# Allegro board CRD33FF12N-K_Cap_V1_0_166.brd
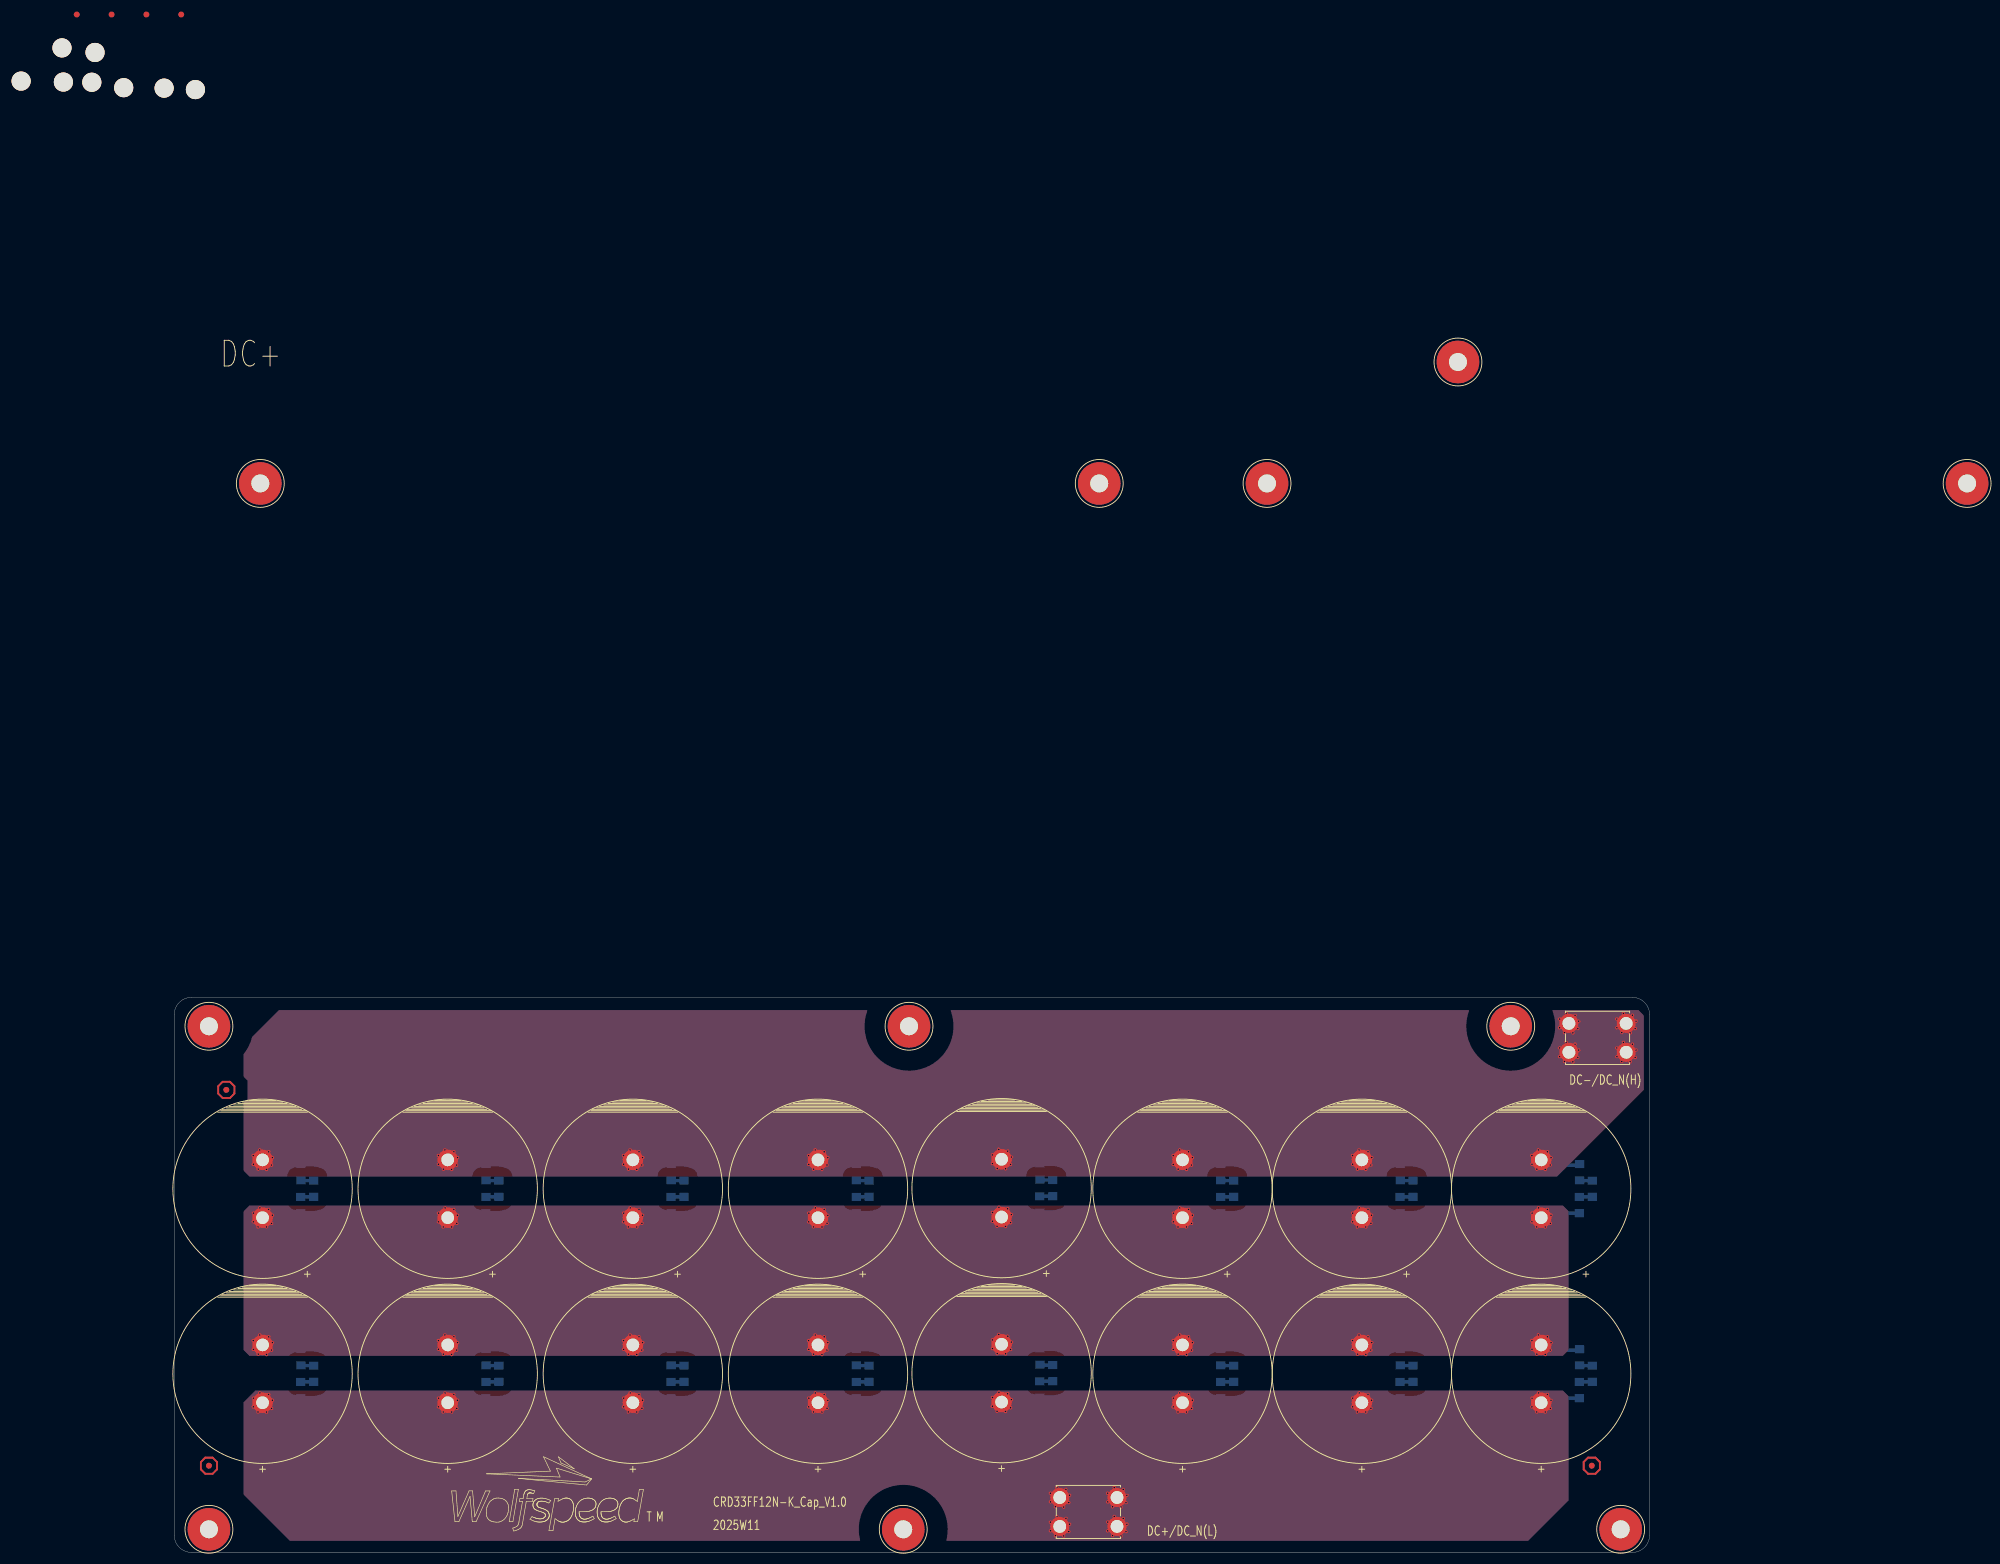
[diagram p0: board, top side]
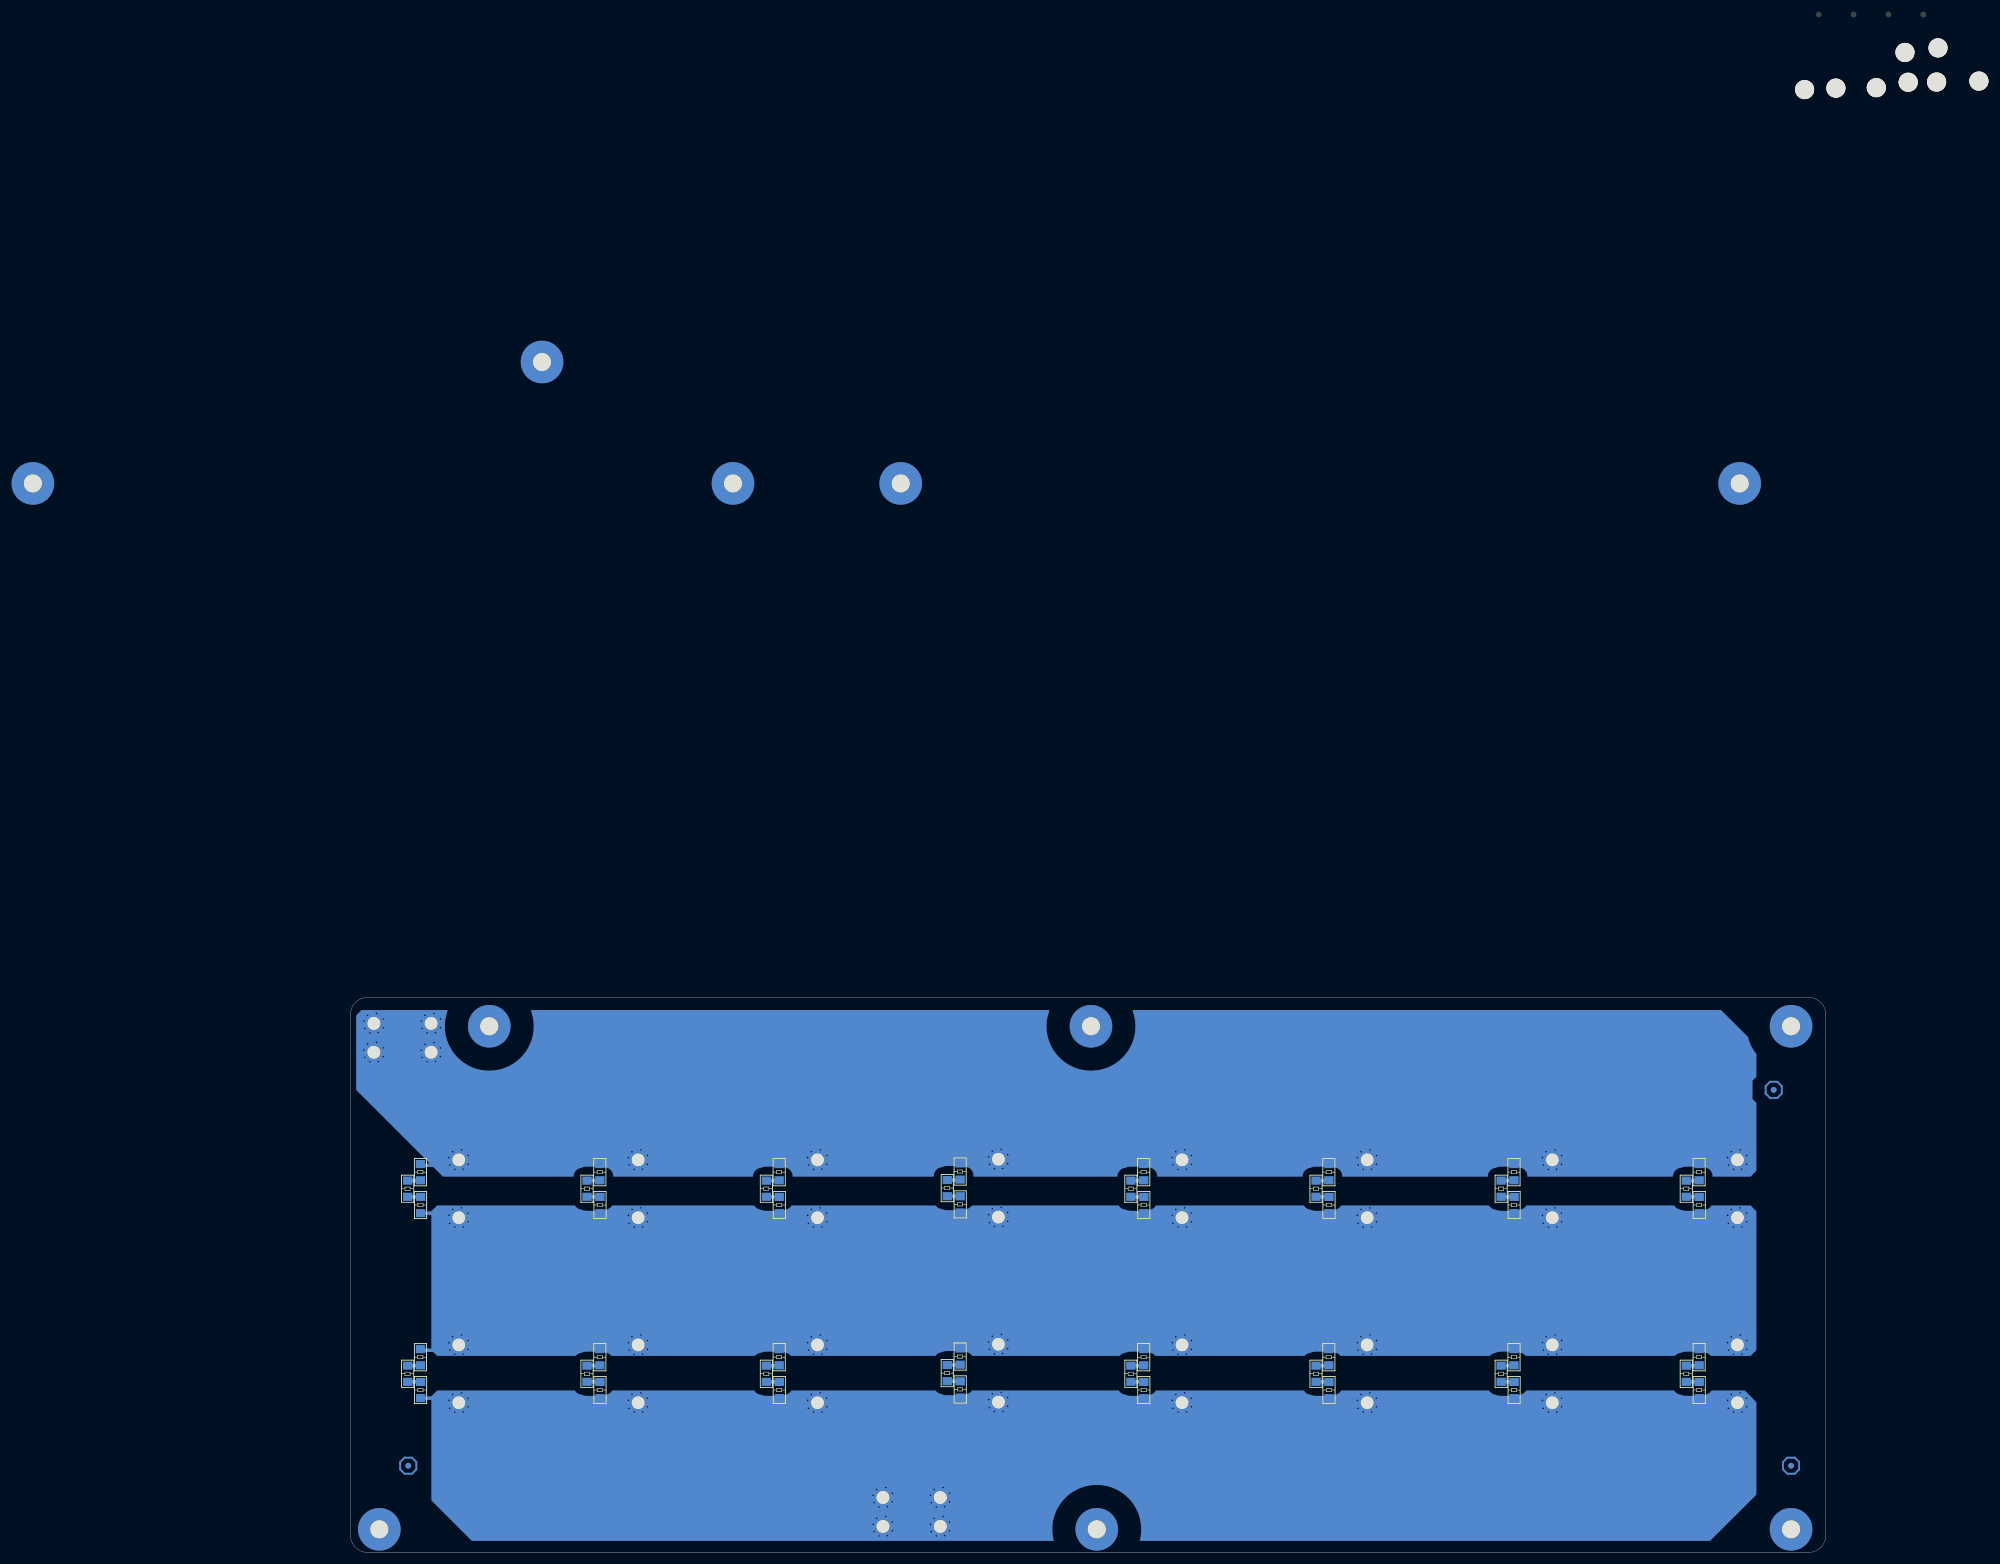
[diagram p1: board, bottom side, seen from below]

Outline 255 x 96 mm; copper layers: TOP, BOTTOM. Coordinates in mm from the lower left corner of the outline.
Outline path: 0,93 0,3 arc(0.88,0.88) 3,0 252,0 arc(254.12,0.88) 255,3 255,93 arc(254.12,95.12) 252,96 3,96 arc(0.88,95.12) 0,93

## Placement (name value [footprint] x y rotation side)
C1  820uF  [CAP2_1000-D3000X6000]  15.27 30.89 90 top
C2  820uF  [CAP2_1000-D3000X6000]  174.27 30.89 90 top
C3  820uF  [CAP2_1000-D3000X6000]  236.27 30.89 90 top
C4  820uF  [CAP2_1000-D3000X6000]  47.27 30.89 90 top
C5  820uF  [CAP2_1000-D3000X6000]  79.27 30.89 90 top
C6  820uF  [CAP2_1000-D3000X6000]  111.27 30.89 90 top
C7  820uF  [CAP2_1000-D3000X6000]  15.27 62.89 90 top
C8  820uF  [CAP2_1000-D3000X6000]  205.27 30.89 90 top
C9  820uF  [CAP2_1000-D3000X6000]  143 31 90 top
C10  820uF  [CAP2_1000-D3000X6000]  47.27 62.89 90 top
C11  820uF  [CAP2_1000-D3000X6000]  79.27 62.89 90 top
C12  820uF  [CAP2_1000-D3000X6000]  111.27 62.89 90 top
C14  820uF  [CAP2_1000-D3000X6000]  174.27 62.89 90 top
C15  820uF  [CAP2_1000-D3000X6000]  205.27 62.89 90 top
C20  820uF  [CAP2_1000-D3000X6000]  236.27 62.89 90 top
C21  820uF  [CAP2_1000-D3000X6000]  143 63 90 top
CON2  Connecter  [THREAD4_9P9X5_1110X920]  246 89 0 top
CON4  Connecter  [THREAD4_9P9X5_1110X920]  158 7 180 top
FD1  -  [FID1X2R]  -4.81 265.98 0 top
FD2  -  [FID1X2R]  1.21 265.98 0 top
FD3  -  [FID1X2R]  -10.83 265.98 0 top
FD4  -  [FID1X2R]  -16.85 265.98 0 top
MT1  Mouting Hole  [MTG330N]  -14.24 254.26 180 bottom
MT2  Mouting Hole  [MTG330N]  -13.68 259.42 0 top
MT3  Mouting Hole  [MTG330N]  -19.16 254.3 0 top
MT4  Mouting Hole  [MTG330N]  -8.73 253.32 180 bottom
MT5  Mouting Hole  [MTG330N]  -26.46 254.46 180 bottom
MT6  Mouting Hole  [MTG330N]  -19.4 260.2 0 top
MT7  Mouting Hole  [MTG330N]  -1.75 253.24 0 top
MT8  Mouting Hole  [MTG330N]  3.66 252.99 270 top
NOREF  #VAL  [unnamed]  6 91 270 top
NOREF#2  -  [#2]  305.52 95.7 0 top
NOREF#3  #VAL  [unnamed]  221.88 205.88 90 top
NOREF#4  #VAL  [unnamed]  250 4 270 top
NOREF#5  #VAL  [unnamed]  159.88 184.88 270 top
NOREF#6  #VAL  [unnamed]  6 4 90 top
NOREF#7  #VAL  [unnamed]  245 15 180 top
NOREF#8  #VAL  [unnamed]  9 80 180 top
NOREF#9  #VAL  [unnamed]  126 4 90 top
NOREF#10  #VAL  [unnamed]  231 91 0 top
NOREF#11  #VAL  [unnamed]  127 91 180 top
NOREF#12  #VAL  [unnamed]  14.88 184.88 90 top
NOREF#13  #VAL  [unnamed]  6 15 180 top
NOREF#14  #VAL  [unnamed]  188.88 184.88 270 top
NOREF#15  #VAL  [unnamed]  309.88 184.88 90 top
NOREF#16  #VAL  [unnamed]  9 80 0 bottom
NOREF#17  #VAL  [unnamed]  6 15 0 bottom
NOREF#18  #VAL  [unnamed]  245 15 0 bottom
R1  470K  [R1206]  180.87 28.08 270 bottom
R2  470K  [R1206]  211.87 28.08 270 bottom
R3  470K  [R1206]  242.87 28.08 270 bottom
R4  470K  [R1206]  21.87 28.08 270 bottom
R5  470K  [R1206]  53.87 28.08 270 bottom
R6  470K  [R1206]  85.87 28.08 270 bottom
R7  470K  [R1206]  117.87 28.08 270 bottom
R8  470K  [R1206]  183.11 30.9 270 bottom
R9  470K  [R1206]  214.11 30.9 270 bottom
R10  470K  [R1206]  245.11 30.9 270 bottom
R11  470K  [R1206]  24.11 30.9 270 bottom
R12  470K  [R1206]  56.11 30.9 270 bottom
R13  470K  [R1206]  88.11 30.9 270 bottom
R14  470K  [R1206]  120.11 30.9 270 bottom
R15  470K  [R1206]  180.89 33.76 270 bottom
R16  470K  [R1206]  211.89 33.76 270 bottom
R17  470K  [R1206]  242.89 33.76 270 bottom
R18  470K  [R1206]  21.89 33.76 270 bottom
R19  470K  [R1206]  53.89 33.76 270 bottom
R20  470K  [R1206]  85.89 33.76 270 bottom
R21  470K  [R1206]  117.89 33.76 270 bottom
R22  470K  [R1206]  242.87 60.08 270 bottom
R23  470K  [R1206]  180.87 60.08 270 bottom
R24  470K  [R1206]  211.87 60.08 270 bottom
R25  470K  [R1206]  21.87 60.08 270 bottom
R26  470K  [R1206]  53.87 60.08 270 bottom
R27  470K  [R1206]  117.87 60.08 270 bottom
R28  470K  [R1206]  85.87 60.08 270 bottom
R29  470K  [R1206]  245.11 62.9 270 bottom
R30  470K  [R1206]  183.11 62.9 270 bottom
R31  470K  [R1206]  214.11 62.9 270 bottom
R32  470K  [R1206]  24.11 62.9 270 bottom
R33  470K  [R1206]  56.11 62.9 270 bottom
R34  470K  [R1206]  120.11 62.9 270 bottom
R35  470K  [R1206]  88.11 62.9 270 bottom
R36  470K  [R1206]  242.89 65.76 270 bottom
R37  470K  [R1206]  180.89 65.76 270 bottom
R38  470K  [R1206]  211.89 65.76 270 bottom
R39  470K  [R1206]  21.89 65.76 270 bottom
R40  470K  [R1206]  53.89 65.76 270 bottom
R41  470K  [R1206]  117.89 65.76 270 bottom
R42  470K  [R1206]  85.89 65.76 270 bottom
R85  470K  [R1206]  149.6 28.19 270 bottom
R86  470K  [R1206]  151.84 31.01 270 bottom
R87  470K  [R1206]  149.62 33.87 270 bottom
R88  470K  [R1206]  149.6 60.19 270 bottom
R89  470K  [R1206]  151.84 63.01 270 bottom
R90  470K  [R1206]  149.62 65.87 270 bottom

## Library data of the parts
C1-C12 C14 C15 C20 C21 = CAP2_1000-D3000X6000: User Part Number: HAMP; Tolerance: #TOL
CON2 CON4 = THREAD4_9P9X5_1110X920: Tolerance: #TOL; User Part Number: HAMP
FD1-FD4 = FID1X2R: Tolerance: #TOL; User Part Number: HAMP
MT1-MT8 = MTG330N: Tolerance: #TOL; User Part Number: HAMP
NOREF NOREF#4-NOREF#18 = -: Tolerance: #TOL; User Part Number: HAMP
NOREF#3 = -: User Part Number: HAMP; Tolerance: #TOL
R1-R42 R85-R90 = R1206: User Part Number: HAMP; Tolerance: #TOL

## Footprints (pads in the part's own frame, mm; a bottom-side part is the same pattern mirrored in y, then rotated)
CAP2_1000-D3000X6000
  round 3.556 hole 2.184: 1(-5,0) 2(5,0)
FID1X2R
  round 1.016 smd: 0(0,0)
MTG330N
  round 3.3 hole 3.3 unplated: (0,0)
R1206
  rect 1.397x1.6 smd: 1(-1.4,0) 2(1.4,0)
THREAD4_9P9X5_1110X920
  round 3.302 hole 2.21: 1(4.95,2.5) 2(-4.95,2.5) 3(-4.95,-2.5) 4(4.95,-2.5)
unnamed
  round 7.366 hole 3.099: 1(0,0)

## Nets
DC+: C1.1 C2.1 C3.1 C4.1 C5.1 C6.1 C8.1 C9.1 CON4.1 CON4.2 CON4.3 CON4.4 R1.2 R2.2 R3.2 R4.2 R5.2 R6.2 R7.2 R85.2
DC-: C7.2 C10.2 C11.2 C12.2 C14.2 C15.2 C20.2 C21.2 CON2.1 CON2.2 CON2.3 CON2.4 R36.1 R37.1 R38.1 R39.1 R40.1 R41.1 R42.1 R90.1
NETC1_2: C1.2 C2.2 C3.2 C4.2 C5.2 C6.2 C7.1 C8.2 C9.2 C10.1 C11.1 C12.1 C14.1 C15.1 C20.1 C21.1 R15.1 R16.1 R17.1 R18.1 R19.1 R20.1 R21.1 R22.2 R23.2 R24.2 R25.2 R26.2 R27.2 R28.2 R87.1 R88.2
NETR1_1: R1.1 R8.2
NETR2_1: R2.1 R9.2
NETR3_1: R3.1 R10.2
NETR4_1: R4.1 R11.2
NETR5_1: R5.1 R12.2
NETR6_1: R6.1 R13.2
NETR7_1: R7.1 R14.2
NETR8_1: R8.1 R15.2
NETR9_1: R9.1 R16.2
NETR10_1: R10.1 R17.2
NETR11_1: R11.1 R18.2
NETR12_1: R12.1 R19.2
NETR13_1: R13.1 R20.2
NETR14_1: R14.1 R21.2
NETR22_1: R22.1 R29.2
NETR23_1: R23.1 R30.2
NETR24_1: R24.1 R31.2
NETR25_1: R25.1 R32.2
NETR26_1: R26.1 R33.2
NETR27_1: R27.1 R34.2
NETR28_1: R28.1 R35.2
NETR29_1: R29.1 R36.2
NETR30_1: R30.1 R37.2
NETR31_1: R31.1 R38.2
NETR32_1: R32.1 R39.2
NETR33_1: R33.1 R40.2
NETR34_1: R34.1 R41.2
NETR35_1: R35.1 R42.2
NETR85_1: R85.1 R86.2
NETR86_1: R86.1 R87.2
NETR88_1: R88.1 R89.2
NETR89_1: R89.1 R90.2

Pads without a net: FD1 0; FD2 0; FD3 0; FD4 0; NOREF 1; NOREF#3 1; NOREF#4 1; NOREF#5 1; NOREF#6 1; NOREF#7 1; NOREF#8 1; NOREF#9 1; NOREF#10 1; NOREF#11 1; NOREF#12 1; NOREF#13 1; NOREF#14 1; NOREF#15 1; NOREF#16 1; NOREF#17 1; NOREF#18 1

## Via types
v1: diameter 0.61, hole 0.305, TOP to BOTTOM, 320 vias

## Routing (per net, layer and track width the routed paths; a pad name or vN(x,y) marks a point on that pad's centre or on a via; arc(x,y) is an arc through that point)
DC+: length 55.4
  BOTTOM w0.6: C4.1 48.06,26.68 R5.2 ; C6.1 112.06,26.68 R7.2 ; R1.2 175.06,26.68 C2.1 ; R2.2 206.06,26.68 C8.1 ; R4.2 16.06,26.68 C1.1 ; R6.2 80.06,26.68 C5.1 ; R3.2 237.06,26.68 C3.1 ; R85.2 143.79,26.79 C9.1
  vias: v1(13.69,26.68) v1(13.66,25.17) v1(14.49,24.29) v1(14.81,27.59) v1(15.95,24.28) v1(16.33,27.33) v1(16.84,24.92) v1(16.96,26.32) v1(45.69,26.68) v1(45.66,25.17) v1(46.49,24.29) v1(46.81,27.59) v1(47.95,24.28) v1(48.33,27.33) v1(48.84,24.92) v1(48.96,26.32) v1(77.69,26.68) v1(77.66,25.17) v1(78.49,24.29) v1(78.81,27.59) v1(79.95,24.28) v1(80.33,27.33) v1(80.84,24.92) v1(80.96,26.32) v1(109.69,26.68) v1(109.66,25.17) v1(110.49,24.29) v1(110.81,27.59) v1(111.95,24.28) v1(112.33,27.33) v1(112.84,24.92) v1(112.96,26.32) v1(141.42,26.79) v1(141.39,25.28) v1(142.22,24.4) v1(142.54,27.69) v1(143.68,24.39) v1(144.06,27.44) v1(144.57,25.03) v1(144.7,26.42) v1(151.44,10.25) v1(151.45,8.74) v1(151.44,5.25) v1(151.45,3.74) v1(152.3,7.9) v1(152.3,2.9) v1(152.56,11.22) v1(152.56,6.22) v1(153.74,7.85) v1(153.74,2.85) v1(154.12,10.9) v1(154.12,5.9) v1(154.6,8.61) v1(154.6,3.61) v1(154.75,9.88) v1(154.75,4.88) v1(161.34,10.25) v1(161.35,8.74) v1(161.34,5.25) v1(161.35,3.74) v1(162.2,7.9) v1(162.2,2.9) v1(162.46,11.22) v1(162.46,6.22) v1(163.64,7.85) v1(163.64,2.85) v1(164.02,10.9) v1(164.02,5.9) v1(164.5,8.61) v1(164.5,3.61) v1(164.65,9.88) v1(164.65,4.88) v1(172.69,26.68) v1(172.66,25.17) v1(173.49,24.29) v1(173.81,27.59) v1(174.95,24.28) v1(175.33,27.33) v1(175.84,24.92) v1(175.96,26.32) v1(203.69,26.68) v1(203.66,25.17) v1(204.49,24.29) v1(204.81,27.59) v1(205.95,24.28) v1(206.33,27.33) v1(206.84,24.92) v1(206.96,26.32) v1(234.69,26.68) v1(234.66,25.17) v1(235.49,24.29) v1(235.81,27.59) v1(236.95,24.28) v1(237.33,27.33) v1(237.84,24.92) v1(237.96,26.32)
DC-: length 56.7
  BOTTOM w0.6: C10.2 48.2,66.96 53.69,66.96 R40.1 ; R42.1 85.69,66.96 80.2,66.96 C11.2 ; C7.2 16.2,66.96 21.69,66.96 R39.1 ; C14.2 175.2,66.96 180.69,66.96 R37.1 ; C21.2 143.93,67.07 149.42,67.07 R90.1 ; C12.2 112.2,66.96 117.69,66.96 R41.1 ; C20.2 237.2,66.96 242.69,66.96 R36.1 ; R38.1 211.69,66.96 206.2,66.96 C15.2
  vias: v1(13.66,68.64) v1(13.67,67.13) v1(14.52,66.29) v1(14.78,69.61) v1(15.96,66.24) v1(16.34,69.29) v1(16.82,67) v1(16.97,68.27) v1(45.66,68.64) v1(45.67,67.13) v1(46.52,66.29) v1(46.78,69.61) v1(47.96,66.24) v1(48.34,69.29) v1(48.82,67) v1(48.97,68.27) v1(77.66,68.64) v1(77.67,67.13) v1(78.52,66.29) v1(78.78,69.61) v1(79.96,66.24) v1(80.34,69.29) v1(80.82,67) v1(80.97,68.27) v1(109.66,68.64) v1(109.67,67.13) v1(110.52,66.29) v1(110.78,69.61) v1(111.96,66.24) v1(112.34,69.29) v1(112.82,67) v1(112.97,68.27) v1(141.39,68.75) v1(141.4,67.24) v1(142.25,66.4) v1(142.51,69.72) v1(143.69,66.35) v1(144.07,69.4) v1(144.55,67.11) v1(144.7,68.38) v1(172.66,68.64) v1(172.67,67.13) v1(173.52,66.29) v1(173.78,69.61) v1(174.96,66.24) v1(175.34,69.29) v1(175.82,67) v1(175.97,68.27) v1(203.66,68.64) v1(203.67,67.13) v1(204.52,66.29) v1(204.78,69.61) v1(205.96,66.24) v1(206.34,69.29) v1(206.82,67) v1(206.97,68.27) v1(234.66,68.64) v1(234.67,67.13) v1(235.52,66.29) v1(235.78,69.61) v1(236.96,66.24) v1(237.34,69.29) v1(237.82,67) v1(237.97,68.27) v1(239.44,92.25) v1(239.45,90.74) v1(239.44,87.25) v1(239.45,85.74) v1(240.3,89.9) v1(240.3,84.9) v1(240.56,93.22) v1(240.56,88.22) v1(241.74,89.85) v1(241.74,84.85) v1(242.12,92.9) v1(242.12,87.9) v1(242.6,90.61) v1(242.6,85.61) v1(242.75,91.88) v1(242.75,86.88) v1(249.34,92.25) v1(249.35,90.74) v1(249.34,87.25) v1(249.35,85.74) v1(250.2,89.9) v1(250.2,84.9) v1(250.46,93.22) v1(250.46,88.22) v1(251.64,89.85) v1(251.64,84.85) v1(252.02,92.9) v1(252.02,87.9) v1(252.5,90.61) v1(252.5,85.61) v1(252.65,91.88) v1(252.65,86.88)
NETC1_2: length 112.1
  BOTTOM w0.6: R18.1 21.69,34.96 16.2,34.96 C1.2 ; R21.1 117.69,34.96 112.2,34.96 C6.2 ; C14.1 175.06,58.68 R23.2 ; R17.1 242.69,34.96 237.2,34.96 C3.2 ; C10.1 48.06,58.68 R26.2 ; R19.1 53.69,34.96 48.2,34.96 C4.2 ; C2.2 175.2,34.96 180.69,34.96 R15.1 ; R20.1 85.69,34.96 80.2,34.96 C5.2 ; R27.2 112.06,58.68 C12.1 ; C11.1 80.06,58.68 R28.2 ; C7.1 16.06,58.68 R25.2 ; C21.1 143.79,58.79 R88.2 ; C9.2 143.93,35.07 149.42,35.07 R87.1 ; C20.1 237.06,58.68 R22.2 ; C8.2 206.2,34.96 211.69,34.96 R16.1 ; R24.2 206.06,58.68 C15.1
  vias: v1(13.69,58.68) v1(13.66,57.17) v1(13.66,36.64) v1(13.67,35.13) v1(14.49,56.29) v1(14.52,34.29) v1(14.81,59.59) v1(14.78,37.61) v1(15.95,56.28) v1(15.96,34.24) v1(16.33,59.33) v1(16.34,37.29) v1(16.82,35) v1(16.84,56.92) v1(16.96,58.32) v1(16.97,36.27) v1(45.69,58.68) v1(45.66,57.17) v1(45.66,36.64) v1(45.67,35.13) v1(46.49,56.29) v1(46.52,34.29) v1(46.81,59.59) v1(46.78,37.61) v1(47.95,56.28) v1(47.96,34.24) v1(48.33,59.33) v1(48.34,37.29) v1(48.82,35) v1(48.84,56.92) v1(48.96,58.32) v1(48.97,36.27) v1(77.69,58.68) v1(77.66,57.17) v1(77.66,36.64) v1(77.67,35.13) v1(78.49,56.29) v1(78.52,34.29) v1(78.81,59.59) v1(78.78,37.61) v1(79.95,56.28) v1(79.96,34.24) v1(80.33,59.33) v1(80.34,37.29) v1(80.82,35) v1(80.84,56.92) v1(80.96,58.32) v1(80.97,36.27) v1(109.69,58.68) v1(109.66,57.17) v1(109.66,36.64) v1(109.67,35.13) v1(110.49,56.29) v1(110.52,34.29) v1(110.81,59.59) v1(110.78,37.61) v1(111.95,56.28) v1(111.96,34.24) v1(112.33,59.33) v1(112.34,37.29) v1(112.82,35) v1(112.84,56.92) v1(112.96,58.32) v1(112.97,36.27) v1(141.42,58.79) v1(141.39,57.28) v1(141.39,36.75) v1(141.4,35.24) v1(142.22,56.4) v1(142.25,34.4) v1(142.51,37.72) v1(142.54,59.69) v1(143.68,56.39) v1(143.69,34.35) v1(144.06,59.44) v1(144.07,37.4) v1(144.57,57.03) v1(144.55,35.11) v1(144.7,58.42) v1(144.7,36.38) v1(172.69,58.68) v1(172.66,57.17) v1(172.66,36.64) v1(172.67,35.13) v1(173.49,56.29) v1(173.52,34.29) v1(173.81,59.59) v1(173.78,37.61) v1(174.95,56.28) v1(174.96,34.24) v1(175.33,59.33) v1(175.34,37.29) v1(175.82,35) v1(175.84,56.92) v1(175.96,58.32) v1(175.97,36.27) v1(203.69,58.68) v1(203.66,57.17) v1(203.66,36.64) v1(203.67,35.13) v1(204.49,56.29) v1(204.52,34.29) v1(204.81,59.59) v1(204.78,37.61) v1(205.95,56.28) v1(205.96,34.24) v1(206.33,59.33) v1(206.34,37.29) v1(206.82,35) v1(206.84,56.92) v1(206.96,58.32) v1(206.97,36.27) v1(234.69,58.68) v1(234.66,57.17) v1(234.66,36.64) v1(234.67,35.13) v1(235.49,56.29) v1(235.52,34.29) v1(235.81,59.59) v1(235.78,37.61) v1(236.95,56.28) v1(236.96,34.24) v1(237.33,59.33) v1(237.34,37.29) v1(237.82,35) v1(237.84,56.92) v1(237.96,58.32) v1(237.97,36.27)
NETR1_1: length 2.2
  BOTTOM w0.6: R1.1 180.89,29.5 R8.2
NETR2_1: length 2.2
  BOTTOM w0.6: R2.1 211.89,29.5 R9.2
NETR3_1: length 2.2
  BOTTOM w0.6: R10.2 242.89,29.5 R3.1
NETR4_1: length 2.2
  BOTTOM w0.6: R4.1 21.89,29.5 R11.2
NETR5_1: length 2.2
  BOTTOM w0.6: R5.1 53.89,29.5 R12.2
NETR6_1: length 2.2
  BOTTOM w0.6: R6.1 85.89,29.5 R13.2
NETR7_1: length 2.2
  BOTTOM w0.6: R7.1 117.89,29.5 R14.2
NETR8_1: length 2.2
  BOTTOM w0.6: R15.2 180.95,32.3 R8.1
NETR9_1: length 2.2
  BOTTOM w0.6: R16.2 211.95,32.3 R9.1
NETR10_1: length 2.2
  BOTTOM w0.6: R10.1 242.95,32.3 R17.2
NETR11_1: length 2.2
  BOTTOM w0.6: R11.1 21.95,32.3 R18.2
NETR12_1: length 2.2
  BOTTOM w0.6: R19.2 53.95,32.3 R12.1
NETR13_1: length 2.2
  BOTTOM w0.6: R20.2 85.95,32.3 R13.1
NETR14_1: length 2.2
  BOTTOM w0.6: R14.1 117.95,32.3 R21.2
NETR22_1: length 2.2
  BOTTOM w0.6: R22.1 242.89,61.5 R29.2
NETR23_1: length 2.2
  BOTTOM w0.6: R30.2 180.89,61.5 R23.1
NETR24_1: length 2.2
  BOTTOM w0.6: R24.1 211.89,61.5 R31.2
NETR25_1: length 2.2
  BOTTOM w0.6: R32.2 21.89,61.5 R25.1
NETR26_1: length 2.2
  BOTTOM w0.6: R33.2 53.89,61.5 R26.1
NETR27_1: length 2.2
  BOTTOM w0.6: R27.1 117.89,61.5 R34.2
NETR28_1: length 2.2
  BOTTOM w0.6: R28.1 85.89,61.5 R35.2
NETR29_1: length 2.2
  BOTTOM w0.6: R29.1 242.95,64.3 R36.2
NETR30_1: length 2.2
  BOTTOM w0.6: R37.2 180.95,64.3 R30.1
NETR31_1: length 2.2
  BOTTOM w0.6: R31.1 211.95,64.3 R38.2
NETR32_1: length 2.2
  BOTTOM w0.6: R32.1 21.95,64.3 R39.2
NETR33_1: length 2.2
  BOTTOM w0.6: R33.1 53.95,64.3 R40.2
NETR34_1: length 2.2
  BOTTOM w0.6: R34.1 117.95,64.3 R41.2
NETR35_1: length 2.2
  BOTTOM w0.6: R42.2 85.95,64.3 R35.1
NETR85_1: length 2.2
  BOTTOM w0.6: R86.2 149.62,29.61 R85.1
NETR86_1: length 2.2
  BOTTOM w0.6: R87.2 149.68,32.41 R86.1
NETR88_1: length 2.2
  BOTTOM w0.6: R89.2 149.62,61.61 R88.1
NETR89_1: length 2.2
  BOTTOM w0.6: R89.1 149.68,64.41 R90.2

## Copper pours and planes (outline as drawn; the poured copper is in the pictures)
DC+ on BOTTOM (solid shape): outline of 103 points within 12,2 241,28
DC+ on TOP: 14,28 240,28 241,27 241,9 234,2 20,2 12,10 12,26
DC- on BOTTOM (solid shape): outline of 143 points within 12,65 254,93.8
DC- on TOP: 239,65 13,65 12,66 12,87.69 18.11,93.8 253.06,93.8 254,92.86 254,80
NETC1_2 on BOTTOM (solid shape): outline of 176 points within 12,34 241,60
NETC1_2 on TOP: 12,59 12,35 13,34 240,34 241,35 241,59 240,60 13,60

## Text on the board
Ref Des/Silkscreen Top: T | M | CRD33FF12N-K_Cap_V1.0 | 2025W11 | DC+/DC_N(L) | DC-/DC_N(H) | DC+
User.21: FIGURE | FINISHED_SIZE | 0.3048 | 2.1844 | 2.2098 | 3.0988 | 3.3 | DRILL CHART: TOP to BOTTOM | ALL UNITS ARE IN MILLIMETERS | PLATED | NON-PLATED | QTY | 320 | 32 | 8 | 11
